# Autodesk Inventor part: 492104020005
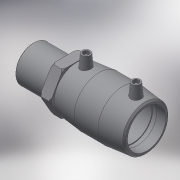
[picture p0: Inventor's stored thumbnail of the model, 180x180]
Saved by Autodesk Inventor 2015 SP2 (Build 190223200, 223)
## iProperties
Created: 2017-06
Part Number: 492104020005
Material: Generic
Description: PLASSON Male Transition Coupler 20 x 1/2"
Document SubType Name: Modeling
Designer: KIM
Mass: 46.8847 g
Surface Area: 198.876 cm^2
Volume: 46.8847 cm^3
Density: 1 g/cm^3
Appearance: Default
Author: KIM
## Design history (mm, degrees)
derived "492104.ipt"
feature "Solid1::492104.ipt"
tag "TaggingFeature1"
body "Solid1"
other parameters: "d0" = 76, "d2" = 31, "d3" = 37, "d4" = 25.33333, "d5" = 27.9, "d6" = 19, "d8" = 168 deg, "d10" = 14.8, "d11" = 4.93333, "d29" = 34, "d30" = 14, "d31" = 26.6, "d34" = 5 deg, "d41" = 4, "d42" = 14, "d43" = 0, "d48" = 3, "d49" = 0, "d57" = 14, "d58" = 20.955, "d59" = 16.764, "d60" = 26.1, "d61" = 29.337, "d62" = 0.4191, "d65" = 0.93, "d70" = 0.1, "d71" = 29, "d72" = 7.25, "d73" = 14.8, "d75" = 0, "L_" = 105, "L_1" = 37, "D_1" = 31, "A_" = 34, "d_2" = 12, "L_2" = 29, "D_" = 14, "R_" = 20.955
